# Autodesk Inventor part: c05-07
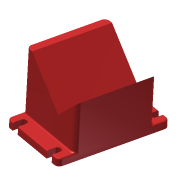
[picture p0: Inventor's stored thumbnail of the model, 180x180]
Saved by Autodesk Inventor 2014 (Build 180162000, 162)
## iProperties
Created: 2010-11
Part Number: c05-07
Material: Generic
Document SubType Name: Modeling
Designer: Thom Tremblay
Density: 1 g/cm^3
Appearance: Satin -Light Red
Author: Thom Tremblay
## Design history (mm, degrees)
sketch "Sketch1"
  geometry: L1 (-45, 0)-(45, 0); L2 (45, 0)-(45, 10); L3 (45, 10)-(-45, 10); L4 (-45, 10)-(-45, 0); L5 (-45, 10)-(-45, 90); L6 (-45, 90)-(-35, 90); L7 (-35, 90)-(14.497, 40.503); L8 (14.497, 40.503)-(45, 71.005); L9 (45, 71.005)-(45, 10); 2 further points
  constraints: 18 end point, 4 perpendicular, 3 collinear, 2 parallel, 2 point on line, 1 coincident, 1 horizontal, 1 midpoint
  dimensions: "d0" = 90 distance of L3.end L2.end; "d1" = 10 distance of L2.end L1.end; "d2" = 80 distance of L5.start L5.end; "d3" = 10 distance of L5.end L6.end; "d4" = 70 distance of L6.end L7.end; "d5" = 135 deg angle of L6 L7
extrude "Extrusion1" new body sketch "Sketch1" stored distance "d8" = 100; taper "d9" = 0 deg
extrude "Extrusion2" join sketch "Sketch1" stored distance "d10" = 140; taper "d11" = 0 deg
fillet "Fillet1" dims "d12" = 6
fillet "Fillet2" dims "d13" = 2
sketch "Sketch2"
  geometry: L1 (78, -2)-(0, -2) reference; L2 (-6, 4)-(-6, 132) reference; L3 (4.5, -2)-(13.5, -2); L4 (13.5, -2)-(13.5, 8); L5 (13.5, 8)-(4.5, 8); L6 (4.5, 8)-(4.5, -2); 2 further points
  constraints: 8 end point, 2 parallel, 1 horizontal, 1 horizontal alignment, 1 midpoint, 1 perpendicular, 1 point on line, 2 other
  dimensions: "d14" = 9 distance of L5.end L4.end; "d15" = 10 distance of L4.end L3.end; "d16" = 15 distance from line of point (9, 8) L2
extrude "Extrusion3" cut sketch "Sketch2" stored distance "d17" = 140; taper "d18" = 0 deg
mirror "Mirror1"
mirror "Mirror2"
body "Solid1"
